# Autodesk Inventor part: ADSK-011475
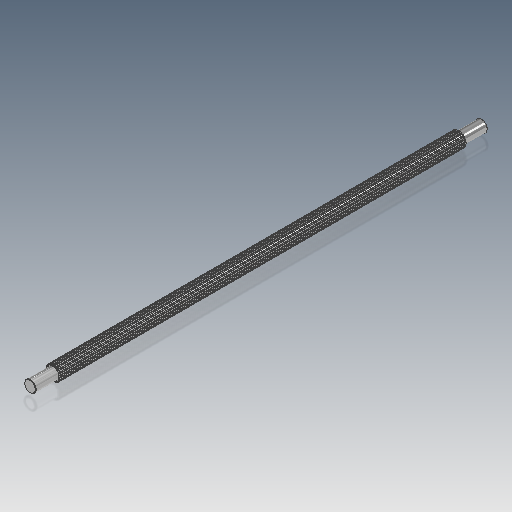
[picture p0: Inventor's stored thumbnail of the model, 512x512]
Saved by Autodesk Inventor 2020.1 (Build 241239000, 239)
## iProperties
Created: 2000-01
Part Number: ADSK-011475
Material: Acier doux
Document SubType Name: Modeling
Designer: tgregory
Density: 7.86 g/cm^3
Appearance: Chrom - poliert
Mass: 5392.88 g
Surface Area: 1417.41 cm^2
Volume: 686.117 cm^3
Control State: 0
Master: False
Checked Out: False
Shininess: 0.0
Length Units: 11269
Angle Units: 11279
Time Units: 11290
Mass Units: 11283
Length Display Precision: 3
Angle Display Precision: 2
Compacted: True
Dimensions: 32x976x32 mm
Mass: 5,393 kg
DocNumber: ADSK-011475.ipt
Folder: 01 - Themengebiete\Simplification\01 - Packaging machine\
VDS_Category: 3D Komponenten
VLT_Material: Acier doux
Density: 0.0
Volumn: 0.0
Area: 0.0
PropertySet Name: Model Information
Author: tgregory
Revision Number: -
Title: shaft
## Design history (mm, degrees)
node "Solide1"
node "Corps solides"
node "Corps surfaciques"
node "Extrusion1" dims "d8" = 876, "d9" = 0
workaxis "Work Axis1"
node "Circular Pattern1" dims "d10" = 200, "d12" = 360 deg
node "Extrusion2" dims "d14" = 50, "d15" = 0
chamfer "Fase1" distance "d19" = 1; stored, may be unused: second distance "d20" = 2, angle "d21" = 45 deg
mirror "Spiegeln1"
sketch "Sketch1"
  geometry: L1 (0, 16)-(0, 0); L2 (1.4, 14.181)-(1.15, 15.959); L3 (-1.15, 15.959)-(-1.4, 14.181); A1 r 14.25 centre (0, 0) between (1.4, 14.181) and (-1.4, 14.181); A2 r 16 centre (0, 0) between (1.15, 15.959) and (-1.15, 15.959); 1 further point
  constraints: 6 end point, 5 point on circle, 3 coincident, 2 centre point, 1 vertical
  dimensions: "d0" = 28.5 diameter of A1; "d1" = 32 diameter of A2; "d4" = 1.15 distance from line of L2.end L1; "d5" = 1.4 distance from line of L2.start L1; "d7" = 1.4 distance from line of L3.end L1 (= d5)
sketch "Sketch2"
  geometry: C1 r 12.5 at (0, 0); A1 r 14.25 centre (0, 0) between (-7.203, -12.296) and (-5.714, -13.054) reference
  constraints: 1 centre point, 1 coincident
  dimensions: "d13" = 25 diameter of C1
